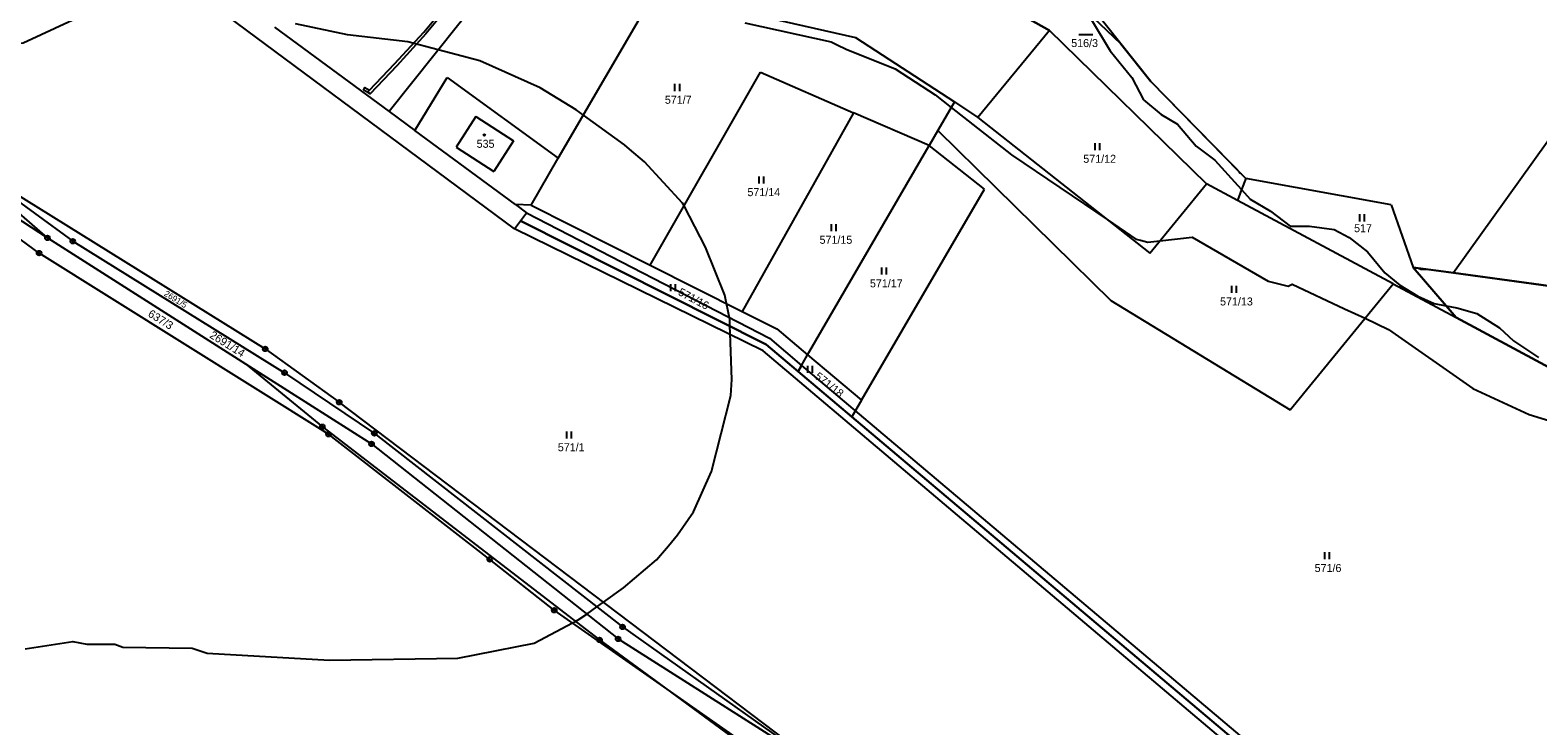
# Model space of a CAD drawing. Extents: x -439246 to -433691, y -1130252 to -1121148.
# Drawn here: x -437509 to -437188.8, y -1124397.9 to -1124250 of the extents above; entities that cross this region are included whole.
import ezdxf

# ---------------------------------------------------------------- set-up
doc = ezdxf.new("R2010")
doc.units = 0
for name, color, linetype in [('Vrstva 1', 7, 'Continuous'), ('Vrstva 18', 7, 'Continuous'), ('Vrstva 19', 7, 'Continuous'), ('Vrstva 24', 7, 'Continuous'), ('Vrstva 25', 7, 'Continuous'), ('Vrstva 3', 7, 'Continuous'), ('Vrstva 30', 7, 'Continuous'), ('Vrstva 37', 7, 'Continuous'), ('Vrstva 4', 7, 'Continuous'), ('Vrstva 52', 7, 'Continuous')]:
    doc.layers.add(name, color=color, linetype=linetype)

msp = doc.modelspace()

# ---------------------------------------------------------------- linework, layer by layer
at = {"layer": 'Vrstva 1'}
for p, q in [((-437410.12, -1124238.76), (-437432.79, -1124267.32)), ((-437507.14, -1124297.4), (-437546.56, -1124268.38)), ((-437432.79, -1124267.32), (-437427.33, -1124271.35)), ((-437405.96, -1124287.09), (-437427.33, -1124271.35)), ((-437523.02, -1124278.02), (-437500, -1124294.87)), ((-437523.02, -1124278.02), (-437459.1, -1124317.77)), ((-437402.64, -1124287.21), (-437405.96, -1124287.09)), ((-437405.96, -1124287.09), (-437403.59, -1124288.84)), ((-437500, -1124294.87), (-437455.01, -1124322.81)), ((-437445.66, -1124335.89), (-437507.14, -1124297.4)), ((-437455.01, -1124322.81), (-437435.93, -1124335.71)), ((-437337.75, -1124409.07), (-437443.38, -1124329.08)), ((-437411.42, -1124362.49), (-437445.66, -1124335.89)), ((-437435.93, -1124335.71), (-437383.21, -1124376.86)), ((-437397.71, -1124373.31), (-437411.42, -1124362.49)), ((-437375.13, -1124389.12), (-437397.71, -1124373.31)), ((-437383.21, -1124376.86), (-437337.75, -1124409.07)), ((-437388.08, -1124379.63), (-437375.13, -1124389.12)), ((-437343.28, -1124411.42), (-437375.13, -1124389.12)), ((-437375.13, -1124389.12), (-437341.75, -1124413.58))]:
    msp.add_line(p, q, dxfattribs=at)
for points in [[(-437406.16, -1124292.25), (-437481.43, -1124236.33)], [(-437396.85, -1124277.22), (-437376.67, -1124242.41)], [(-437305.41, -1124242.79), (-437292.51, -1124250.1)], [(-437361.62, -1124245.22), (-437333.75, -1124251.54)], [(-437271.03, -1124260.94), (-437283.71, -1124244.9)], [(-437457.15, -1124249.38), (-437432.79, -1124267.32)], [(-437292.51, -1124250.1), (-437307.73, -1124268.53)], [(-437259.15, -1124282.66), (-437292.51, -1124250.1)], [(-437333.75, -1124251.54), (-437312.73, -1124265.26)], [(-437172.64, -1124254.01), (-437206.7, -1124301.6)], [(-437427.33, -1124271.35), (-437420.44, -1124260.05)], [(-437420.44, -1124260.05), (-437396.85, -1124277.22)], [(-437377.31, -1124299.96), (-437353.94, -1124258.94)], [(-437353.94, -1124258.94), (-437334.12, -1124267.54)], [(-437250.82, -1124281.53), (-437271.03, -1124260.94)], [(-437312.73, -1124265.26), (-437316.24, -1124271.32)], [(-437312.73, -1124265.26), (-437307.73, -1124268.53)], [(-437334.12, -1124267.54), (-437357.82, -1124309.77)], [(-437318.08, -1124274.49), (-437334.12, -1124267.54)], [(-437307.73, -1124268.53), (-437271.23, -1124297.43)], [(-437540.57, -1124271.21), (-437505.37, -1124294.16)], [(-437316.24, -1124271.32), (-437318.08, -1124274.49)], [(-437316.24, -1124271.32), (-437279.46, -1124307.49)], [(-437505.37, -1124294.16), (-437526.08, -1124276.12)], [(-437343.9, -1124319.01), (-437318.08, -1124274.49)], [(-437306.31, -1124283.78), (-437318.08, -1124274.49)], [(-437402.64, -1124287.21), (-437396.85, -1124277.22)], [(-437271.23, -1124297.43), (-437259.15, -1124282.66)], [(-437252.58, -1124286.18), (-437259.15, -1124282.66)], [(-437250.82, -1124281.53), (-437251.72, -1124283.9)], [(-437219.97, -1124287.11), (-437250.82, -1124281.53)], [(-437332.42, -1124328.68), (-437306.31, -1124283.78)], [(-437251.72, -1124283.9), (-437252.58, -1124286.18)], [(-437219.5, -1124303.93), (-437252.58, -1124286.18)], [(-437404.88, -1124290.56), (-437403.59, -1124288.84)], [(-437402.64, -1124287.21), (-437377.31, -1124299.96)], [(-437219.97, -1124287.11), (-437215.25, -1124300.43)], [(-437406.16, -1124292.25), (-437404.88, -1124290.56)], [(-437352.68, -1124316.84), (-437404.88, -1124290.56)], [(-437505.37, -1124294.16), (-437463.31, -1124320.9)], [(-437377.31, -1124299.96), (-437357.82, -1124309.77)], [(-437206.7, -1124301.6), (-437215.25, -1124300.43)], [(-437215.25, -1124300.43), (-437208.29, -1124308.57)], [(-437174.14, -1124306.08), (-437206.7, -1124301.6)], [(-437230.62, -1124317.54), (-437219.5, -1124303.93)], [(-437219.5, -1124303.93), (-437206.12, -1124311.11)], [(-437279.46, -1124307.49), (-437241.38, -1124330.69)], [(-437208.29, -1124308.57), (-437206.12, -1124311.11)], [(-437357.82, -1124309.77), (-437350.46, -1124313.48)], [(-437206.12, -1124311.11), (-437181.66, -1124324.23)], [(-437350.46, -1124313.48), (-437343.9, -1124319.01)], [(-437459.1, -1124317.77), (-437443.38, -1124329.08)], [(-437345.94, -1124322.53), (-437352.68, -1124316.84)], [(-437241.38, -1124330.69), (-437230.62, -1124317.54)], [(-437463.31, -1124320.9), (-437446.96, -1124334.29)], [(-437463.31, -1124320.9), (-437436.52, -1124337.94)], [(-437345.94, -1124322.53), (-437343.9, -1124319.01)], [(-437343.9, -1124319.01), (-437332.42, -1124328.68)], [(-437334.48, -1124332.22), (-437345.94, -1124322.53)], [(-437332.42, -1124328.68), (-437334.48, -1124332.22)], [(-437446.96, -1124334.29), (-437388.08, -1124379.63)], [(-437334.48, -1124332.22), (-437187.91, -1124456.04)], [(-437436.52, -1124337.94), (-437384.16, -1124379.39)], [(-437384.16, -1124379.39), (-437346.57, -1124403.24)]]:
    msp.add_lwpolyline(points, dxfattribs=at)
at = {"layer": 'Vrstva 24'}
for centre, radius in [((-437505.37, -1124294.16), 0.5), ((-437505.37, -1124294.16), 0.1), ((-437500, -1124294.87), 0.5), ((-437500, -1124294.87), 0.1), ((-437507.14, -1124297.4), 0.5), ((-437507.14, -1124297.4), 0.1), ((-437459.1, -1124317.77), 0.5), ((-437459.1, -1124317.77), 0.1), ((-437455.01, -1124322.81), 0.5), ((-437455.01, -1124322.81), 0.1), ((-437443.38, -1124329.08), 0.5), ((-437443.38, -1124329.08), 0.1), ((-437446.96, -1124334.29), 0.5), ((-437446.96, -1124334.29), 0.1), ((-437445.66, -1124335.89), 0.5), ((-437445.66, -1124335.89), 0.1), ((-437436.52, -1124337.94), 0.5), ((-437435.93, -1124335.71), 0.5), ((-437435.93, -1124335.71), 0.1), ((-437436.52, -1124337.94), 0.1), ((-437411.42, -1124362.49), 0.5), ((-437411.42, -1124362.49), 0.1), ((-437397.71, -1124373.31), 0.5), ((-437397.71, -1124373.31), 0.1), ((-437388.08, -1124379.63), 0.5), ((-437384.16, -1124379.39), 0.5), ((-437384.16, -1124379.39), 0.1), ((-437383.21, -1124376.86), 0.5), ((-437383.21, -1124376.86), 0.1), ((-437388.08, -1124379.63), 0.1)]:
    msp.add_circle(centre, radius, dxfattribs=at)
at = {"layer": 'Vrstva 25'}
for p, q in [((-437286.3, -1124250.9), (-437283.3, -1124250.9)), ((-437372.07, -1124262.94), (-437372.07, -1124261.44)), ((-437371.07, -1124262.94), (-437371.07, -1124261.44)), ((-437282.84, -1124275.49), (-437282.84, -1124273.99)), ((-437281.84, -1124275.49), (-437281.84, -1124273.99)), ((-437354.17, -1124282.58), (-437354.17, -1124281.08)), ((-437353.17, -1124282.58), (-437353.17, -1124281.08)), ((-437226.63, -1124290.64), (-437226.63, -1124289.14)), ((-437225.63, -1124290.64), (-437225.63, -1124289.14)), ((-437338.86, -1124292.71), (-437338.86, -1124291.21)), ((-437337.86, -1124292.71), (-437337.86, -1124291.21)), ((-437328.15, -1124301.97), (-437328.15, -1124300.47)), ((-437327.15, -1124301.97), (-437327.15, -1124300.47)), ((-437372.96, -1124305.46), (-437372.96, -1124303.96)), ((-437371.96, -1124305.46), (-437371.96, -1124303.96)), ((-437253.79, -1124305.82), (-437253.79, -1124304.32)), ((-437252.79, -1124305.82), (-437252.79, -1124304.32)), ((-437343.83, -1124322.87), (-437343.83, -1124321.37)), ((-437342.83, -1124322.87), (-437342.83, -1124321.37)), ((-437395.04, -1124336.81), (-437395.04, -1124335.31)), ((-437394.04, -1124336.81), (-437394.04, -1124335.31)), ((-437234.01, -1124362.48), (-437234.01, -1124360.98)), ((-437233.01, -1124362.48), (-437233.01, -1124360.98))]:
    msp.add_line(p, q, dxfattribs=at)
msp.add_circle((-437412.58, -1124272.3), 0.175, dxfattribs=at)
at = {"layer": 'Vrstva 3'}
for points in [[(-437414.35, -1124268.36), (-437418.57, -1124274.89)], [(-437414.35, -1124268.36), (-437406.35, -1124273.54)], [(-437406.35, -1124273.54), (-437410.57, -1124280.06)], [(-437418.57, -1124274.89), (-437410.57, -1124280.06)]]:
    msp.add_lwpolyline(points, dxfattribs=at)
at = {"layer": 'Vrstva 30'}
for points in [[(-437425.45, -1124250.41), (-437419.42, -1124243.1), (-437413.31, -1124236.02), (-437412.1, -1124235.99), (-437410.95, -1124236.87), (-437410.43, -1124237.18), (-437410.81, -1124237.72), (-437412.3, -1124236.6), (-437413.03, -1124236.61), (-437418.96, -1124243.49), (-437425, -1124250.8)], [(-437431.18, -1124257.57), (-437436.79, -1124263.53), (-437437.36, -1124263.21), (-437436.97, -1124262.75), (-437431.62, -1124257.17), (-437425.45, -1124250.41)], [(-437425, -1124250.8), (-437431.18, -1124257.57)], [(-437438.25, -1124262.72), (-437437.96, -1124262.2), (-437436.97, -1124262.75), (-437437.36, -1124263.21), (-437438.25, -1124262.72)], [(-437403.59, -1124288.84), (-437352, -1124315.5), (-437345.2, -1124321.25), (-437345.94, -1124322.53), (-437352.68, -1124316.84), (-437404.88, -1124290.56), (-437403.59, -1124288.84)], [(-437353.35, -1124318.18), (-437406.16, -1124292.25), (-437404.88, -1124290.56), (-437352.68, -1124316.84), (-437334.48, -1124332.22), (-437187.91, -1124456.04)], [(-437188.73, -1124457.46), (-437353.35, -1124318.18)], [(-437345.2, -1124321.25), (-437187.19, -1124454.8), (-437187.91, -1124456.04), (-437334.48, -1124332.22), (-437345.94, -1124322.53), (-437345.2, -1124321.25)]]:
    msp.add_lwpolyline(points, dxfattribs=at)
at = {"layer": 'Vrstva 37'}
msp.add_circle((-437412.58, -1124272.3), 0.175, dxfattribs=at)
at = {"layer": 'Vrstva 4'}
for points in [[(-437283.61, -1124247.8), (-437279.63, -1124254.42)], [(-437279.63, -1124254.42), (-437275, -1124260.09)], [(-437275, -1124260.09), (-437272.57, -1124264.83)], [(-437272.57, -1124264.83), (-437268.83, -1124267.96)], [(-437414.35, -1124268.36), (-437418.57, -1124274.89)], [(-437414.35, -1124268.36), (-437406.35, -1124273.54)], [(-437268.83, -1124267.96), (-437265.31, -1124270)], [(-437265.31, -1124270), (-437261.35, -1124274.63)], [(-437406.35, -1124273.54), (-437410.57, -1124280.06)], [(-437418.57, -1124274.89), (-437410.57, -1124280.06)], [(-437261.35, -1124274.63), (-437257.39, -1124277.65)], [(-437257.39, -1124277.65), (-437252.54, -1124283)], [(-437252.54, -1124283), (-437251.72, -1124283.9)], [(-437251.72, -1124283.9), (-437249.87, -1124285.92)], [(-437249.87, -1124285.92), (-437245.57, -1124288.51)], [(-437245.57, -1124288.51), (-437241.4, -1124291.64)], [(-437241.4, -1124291.64), (-437237.3, -1124291.64)], [(-437237.3, -1124291.64), (-437232.03, -1124292.37)], [(-437232.03, -1124292.37), (-437228.87, -1124294.07)], [(-437228.87, -1124294.07), (-437224.94, -1124297.11)], [(-437224.94, -1124297.11), (-437221.29, -1124301.56)], [(-437221.29, -1124301.56), (-437218.14, -1124304.21)], [(-437218.14, -1124304.21), (-437214.25, -1124306.56)], [(-437214.25, -1124306.56), (-437210.82, -1124308.07)], [(-437210.82, -1124308.07), (-437208.29, -1124308.57)], [(-437208.29, -1124308.57), (-437205.99, -1124309.03)], [(-437205.99, -1124309.03), (-437201.74, -1124310.26)], [(-437201.74, -1124310.26), (-437196.95, -1124313.31)], [(-437196.95, -1124313.31), (-437193.97, -1124316.02)], [(-437193.97, -1124316.02), (-437188.68, -1124319.56)]]:
    msp.add_lwpolyline(points, dxfattribs=at)
at = {"layer": 'Vrstva 52'}
for points in [[(-437259.15, -1124282.66), (-437292.51, -1124250.1), (-437305.41, -1124242.79), (-437311.38, -1124239.41), (-437321.98, -1124233.41), (-437328.51, -1124229.71), (-437348.84, -1124218.2), (-437361.43, -1124209.27), (-437349.16, -1124215.82), (-437332.5, -1124225.95), (-437324.62, -1124230.6), (-437310.83, -1124238.73), (-437309.96, -1124239.25), (-437299.31, -1124243.09), (-437292.49, -1124244.58), (-437290.24, -1124244.72), (-437289.11, -1124244.79), (-437287.23, -1124244.9)], [(-437499.92, -1124247.8), (-437500, -1124247.84), (-437510.55, -1124252.73), (-437530.95, -1124253.79), (-437544.55, -1124254.01), (-437552.19, -1124253.16), (-437564.3, -1124253.86), (-437572.79, -1124254.35), (-437574.69, -1124254.46), (-437585.34, -1124255.07), (-437592.99, -1124254.01), (-437636.33, -1124253.37), (-437651.63, -1124250.82), (-437659.28, -1124248.06), (-437664.46, -1124245.04)], [(-437287.23, -1124244.9), (-437286.89, -1124245.39), (-437285.57, -1124245.19), (-437285.49, -1124245.18), (-437281.86, -1124248.62), (-437277.45, -1124252.81), (-437271.03, -1124260.94), (-437252.31, -1124280.01), (-437252.01, -1124280.37), (-437251.78, -1124280.55), (-437250.82, -1124281.53), (-437251.72, -1124283.9), (-437252.58, -1124286.18), (-437259.15, -1124282.66)], [(-437510.12, -1124381.49), (-437500, -1124379.99), (-437497, -1124380.49), (-437491.03, -1124380.49), (-437489.33, -1124381.13), (-437474.63, -1124381.34), (-437471.43, -1124382.41), (-437445.44, -1124383.9), (-437418.18, -1124383.47), (-437401.99, -1124380.28), (-437393.84, -1124376.02), (-437393.2, -1124375.68), (-437392.61, -1124375.38), (-437390.83, -1124374.11), (-437388.69, -1124372.59), (-437387.26, -1124371.57), (-437383.03, -1124368.56), (-437376, -1124362.59), (-437373.48, -1124359.6), (-437371.52, -1124357.27), (-437368.11, -1124352.37), (-437364.28, -1124343.85), (-437360.23, -1124327.66), (-437360.02, -1124324.25), (-437360.35, -1124314.43), (-437360.4, -1124312.95), (-437360.45, -1124311.47), (-437361.15, -1124308.09), (-437361.51, -1124306.35), (-437365.56, -1124296.13), (-437370.14, -1124287.37), (-437370.46, -1124286.76), (-437378.55, -1124278.02), (-437381.76, -1124275.3), (-437382.82, -1124274.4), (-437391.53, -1124268.04), (-437393.04, -1124266.94), (-437400.71, -1124262.26), (-437413.49, -1124256.51), (-437422.35, -1124254.17), (-437428.83, -1124252.46), (-437441.61, -1124250.97), (-437452.69, -1124248.62)], [(-437357.25, -1124248.41), (-437338.93, -1124252.46), (-437337.6, -1124253.12), (-437335.72, -1124254.06), (-437325.3, -1124258.21), (-437316.78, -1124263.75), (-437313.4, -1124266.42), (-437300.59, -1124276.53), (-437280.08, -1124290.42), (-437274.17, -1124294.43), (-437273.19, -1124294.67), (-437271.61, -1124295.06), (-437269.06, -1124294.77), (-437262.24, -1124294), (-437246.05, -1124303.37), (-437241.79, -1124304.44), (-437240.94, -1124304.01), (-437229.83, -1124309.22), (-437225.48, -1124311.25), (-437220.49, -1124313.6), (-437202.59, -1124326.17), (-437190.66, -1124331.71), (-437171.92, -1124337.46)], [(-437082.05, -1124367.61), (-437093.53, -1124359.94), (-437119.55, -1124343.94), (-437122.83, -1124343.78), (-437130.68, -1124343.31), (-437156.25, -1124333.74), (-437181.66, -1124324.23), (-437206.12, -1124311.11), (-437208.29, -1124308.57), (-437215.25, -1124300.43), (-437214.13, -1124300.58)], [(-437214.13, -1124300.58), (-437213.67, -1124300.82), (-437212.42, -1124300.82), (-437206.7, -1124301.6), (-437174.76, -1124305.99)]]:
    msp.add_lwpolyline(points, dxfattribs=at)

# ---------------------------------------------------------------- texts
at = {"layer": 'Vrstva 18'}
for s, p in [('516/3', (-437287.91, -1124253.59)), ('571/7', (-437374.23, -1124265.64)), ('571/12', (-437285.34, -1124278.19)), ('571/14', (-437356.68, -1124285.28)), ('517', (-437227.82, -1124292.94)), ('571/15', (-437341.36, -1124295.41)), ('571/17', (-437330.66, -1124304.67)), ('571/13', (-437256.29, -1124308.52)), ('571/1', (-437396.96, -1124339.51)), ('571/6', (-437236.2, -1124365.18))]:
    msp.add_text(s, height=1.7, dxfattribs=at).set_placement(p)
for s, height, rotation, p in [('2691/5', 1.3, 328.0858, (-437480.73, -1124306.34)), ('571/16', 1.7, 331.7729, (-437371.56, -1124306.2)), ('637/3', 1.7, 327.9511, (-437484.17, -1124310.72)), ('2691/14', 1.7, 328.1586, (-437471.07, -1124315.26)), ('571/18', 1.7, 321.7598, (-437342.54, -1124323.88))]:
    msp.add_text(s, height=height, rotation=rotation, dxfattribs=at).set_placement(p)
at = {"layer": 'Vrstva 19'}
msp.add_text('535', height=1.7, dxfattribs=at).set_placement((-437414.2, -1124275))

doc.saveas('drawing.dxf')
